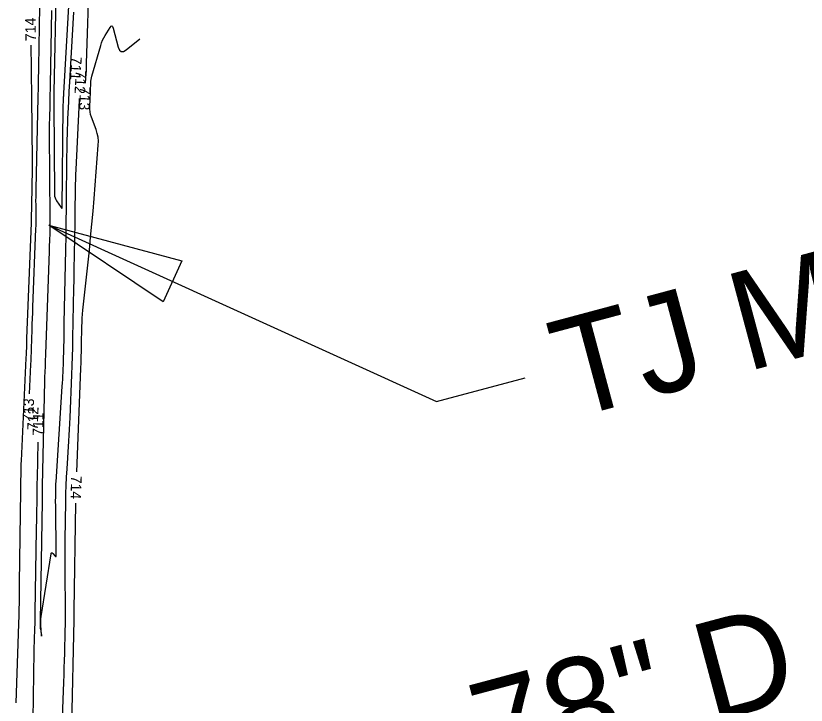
# Model space of a CAD drawing. Extents: x -361782338 to 28259792, y -263199453 to 8342113.
# Drawn here: x 1403883.2 to 1404183.4, y 578042.3 to 578304.2 of the extents above; entities that cross this region are included whole.
import ezdxf

# ---------------------------------------------------------------- set-up
doc = ezdxf.new("R2010")
doc.units = 0
for name, color, linetype in [('DT_X_Contour_Minor', 7, 'Continuous'), ('Level 19', 7, 'Continuous'), ('Level 40', 7, 'Continuous')]:
    doc.layers.add(name, color=color, linetype=linetype)

msp = doc.modelspace()

# ---------------------------------------------------------------- linework, layer by layer
at = {"layer": 'DT_X_Contour_Minor'}
for points in [[(1403900.29, 578367.2), (1403898.68, 578324.89), (1403898.65, 578324.11), (1403898.63, 578323.33), (1403898.61, 578322.55), (1403898.59, 578321.77), (1403898.55, 578319.22), (1403898.54, 578318.67), (1403898.53, 578318.13), (1403898.51, 578317.58), (1403898.5, 578317.03), (1403897.68, 578275.22), (1403897.67, 578274.75), (1403897.66, 578274.28), (1403897.65, 578273.81), (1403897.64, 578273.35), (1403897.6, 578271.81), (1403897.6, 578271.49), (1403897.59, 578271.16), (1403897.59, 578270.83), (1403897.59, 578270.5)], [(1403892.48, 578323.08), (1403891.81, 578284.88), (1403891.79, 578283.71), (1403891.77, 578282.55), (1403891.74, 578281.38), (1403891.72, 578280.21), (1403891.65, 578276.4), (1403891.63, 578275.58), (1403891.61, 578274.77), (1403891.6, 578273.95), (1403891.58, 578273.13), (1403890.78, 578238.34), (1403890.75, 578236.86), (1403890.74, 578235.37), (1403890.73, 578233.89), (1403890.74, 578232.4), (1403890.78, 578227.55), (1403890.78, 578226.51), (1403890.78, 578225.47), (1403890.75, 578224.43), (1403890.72, 578223.39), (1403889.57, 578193.43), (1403889.49, 578191.27), (1403889.41, 578189.12), (1403889.34, 578186.96), (1403889.26, 578184.81), (1403889.02, 578177.76), (1403888.97, 578176.25), (1403888.91, 578174.74), (1403888.84, 578173.24), (1403888.77, 578171.73), (1403888.25, 578160.57)], [(1403909.71, 578278.52), (1403909.93, 578282.21), (1403909.98, 578283.17), (1403910.03, 578284.13), (1403910.07, 578285.08), (1403910.1, 578286.04), (1403911.22, 578320.68)], [(1403897.59, 578270.5), (1403897.89, 578236.36), (1403897.94, 578235.68), (1403898.09, 578235.04), (1403898.34, 578234.43), (1403898.67, 578233.85), (1403900.43, 578231.28), (1403900.46, 578231.24), (1403900.49, 578231.22), (1403900.52, 578231.19), (1403900.56, 578231.17), (1403900.69, 578231.11), (1403900.72, 578231.1), (1403900.74, 578231.11), (1403900.75, 578231.12), (1403900.75, 578231.15), (1403901.22, 578269.6), (1403901.23, 578270.11), (1403901.24, 578270.63), (1403901.26, 578271.15), (1403901.28, 578271.66), (1403901.36, 578273.35), (1403901.38, 578273.71), (1403901.4, 578274.07), (1403901.42, 578274.43), (1403901.44, 578274.79), (1403903.86, 578316.79)], [(1403892.45, 578074.21), (1403892.42, 578072.56), (1403892.42, 578072.21), (1403892.44, 578071.85), (1403892.47, 578071.5), (1403892.52, 578071.14), (1403892.9, 578068.91), (1403892.97, 578068.55), (1403893, 578068.44), (1403893.01, 578068.56), (1403892.99, 578068.92), (1403892.72, 578072.7), (1403892.69, 578073.51), (1403892.7, 578074.31), (1403892.75, 578075.12), (1403892.85, 578075.92), (1403896.56, 578099.73), (1403896.65, 578100.05), (1403896.79, 578100.19), (1403896.99, 578100.15), (1403897.23, 578099.92), (1403898.13, 578098.89), (1403898.3, 578098.73), (1403898.41, 578098.7), (1403898.48, 578098.8), (1403898.51, 578099.03), (1403898.33, 578118.4), (1403898.32, 578119.26), (1403898.32, 578120.13), (1403898.33, 578120.99), (1403898.34, 578121.85), (1403898.38, 578124.67), (1403898.4, 578125.27), (1403898.42, 578125.87), (1403898.44, 578126.48), (1403898.48, 578127.08), (1403900.85, 578163.37), (1403900.93, 578164.7), (1403901, 578166.02), (1403901.07, 578167.35), (1403901.12, 578168.68), (1403901.29, 578173.01), (1403901.33, 578173.94), (1403901.36, 578174.87), (1403901.38, 578175.8), (1403901.4, 578176.73), (1403901.52, 578182.51), (1403901.54, 578183.75), (1403901.57, 578184.99), (1403901.59, 578186.23), (1403901.62, 578187.47), (1403902.16, 578215.27), (1403902.26, 578220.56), (1403902.35, 578225.84), (1403902.43, 578231.13), (1403902.5, 578236.42), (1403902.75, 578257.12), (1403902.79, 578259.1), (1403902.84, 578261.09), (1403902.9, 578263.07), (1403902.99, 578265.05), (1403903.29, 578271.53), (1403903.36, 578272.91), (1403903.43, 578274.3), (1403903.51, 578275.69), (1403903.58, 578277.08), (1403905.23, 578305.54)], [(1403896.78, 578306.21), (1403896.22, 578278.06), (1403896.18, 578276.23), (1403896.15, 578274.4), (1403896.11, 578272.57), (1403896.06, 578270.75), (1403895.93, 578264.77), (1403895.9, 578263.49), (1403895.89, 578262.21), (1403895.89, 578260.93), (1403895.89, 578259.65), (1403896.17, 578227.35), (1403896.17, 578226.08), (1403896.16, 578224.81), (1403896.14, 578223.54), (1403896.1, 578222.28), (1403895.94, 578218.13), (1403895.9, 578217.25), (1403895.87, 578216.36), (1403895.84, 578215.47), (1403895.81, 578214.58), (1403894.48, 578175.72), (1403894.44, 578174.7), (1403894.4, 578173.68), (1403894.36, 578172.65), (1403894.31, 578171.63), (1403894.16, 578168.29), (1403894.13, 578167.57), (1403894.1, 578166.85), (1403894.08, 578166.14), (1403894.06, 578165.42), (1403893.26, 578125.55), (1403893.25, 578124.96), (1403893.24, 578124.38), (1403893.23, 578123.8), (1403893.22, 578123.22), (1403893.2, 578121.31), (1403893.19, 578120.91), (1403893.19, 578120.5), (1403893.18, 578120.09), (1403893.18, 578119.68), (1403892.45, 578074.35), (1403892.45, 578074.34), (1403892.45, 578074.33), (1403892.45, 578074.31), (1403892.45, 578074.3), (1403892.45, 578074.25), (1403892.45, 578074.24), (1403892.45, 578074.23), (1403892.45, 578074.22), (1403892.45, 578074.21)], [(1403906.37, 578130.97), (1403907.91, 578170.21), (1403907.99, 578172.4), (1403908.06, 578174.6), (1403908.12, 578176.8), (1403908.17, 578179), (1403908.31, 578186.18), (1403908.36, 578187.72), (1403908.44, 578189.25), (1403908.55, 578190.79), (1403908.7, 578192.32), (1403911.12, 578215.18), (1403911.62, 578220.08), (1403912.09, 578224.98), (1403912.52, 578229.89), (1403912.92, 578234.8), (1403914.5, 578255.06), (1403914.54, 578256.57), (1403914.41, 578258.05), (1403914.12, 578259.51), (1403913.67, 578260.95), (1403911.93, 578265.61), (1403911.61, 578266.61), (1403911.39, 578267.63), (1403911.28, 578268.67), (1403911.28, 578269.73), (1403911.53, 578275.12), (1403911.54, 578275.18), (1403911.54, 578275.24), (1403911.54, 578275.29), (1403911.55, 578275.35), (1403911.56, 578275.54), (1403911.56, 578275.58), (1403911.56, 578275.62), (1403911.56, 578275.66), (1403911.56, 578275.7), (1403911.66, 578278.69), (1403911.7, 578279.33), (1403911.78, 578279.96), (1403911.9, 578280.59), (1403912.06, 578281.21), (1403915.45, 578292.86), (1403915.78, 578293.87), (1403916.18, 578294.86), (1403916.64, 578295.81), (1403917.18, 578296.74), (1403919.03, 578299.71), (1403919.4, 578300.18), (1403919.72, 578300.3), (1403919.98, 578300.09), (1403920.2, 578299.53), (1403922.13, 578292.21), (1403922.59, 578291.12), (1403923.23, 578290.59), (1403924.06, 578290.64), (1403925.07, 578291.24), (1403930.24, 578295.4)], [(1403888.88, 578293.01), (1403889.02, 578284.14), (1403889.03, 578283.06), (1403889.05, 578281.98), (1403889.07, 578280.9), (1403889.08, 578279.82), (1403889.14, 578276.3), (1403889.15, 578275.54), (1403889.16, 578274.79), (1403889.17, 578274.03), (1403889.17, 578273.28), (1403889.35, 578249.11), (1403889.36, 578246.49), (1403889.35, 578243.87), (1403889.32, 578241.26), (1403889.27, 578238.64), (1403889, 578226.65), (1403889, 578226.54), (1403889, 578226.43), (1403889, 578226.32), (1403889, 578226.2), (1403889, 578225.84), (1403889, 578225.77), (1403889, 578225.69), (1403889, 578225.61), (1403889, 578225.54), (1403887.31, 578181.52), (1403887.28, 578180.78), (1403887.26, 578180.04), (1403887.23, 578179.3), (1403887.2, 578178.56), (1403887.12, 578176.14), (1403887.1, 578175.62), (1403887.08, 578175.1), (1403887.06, 578174.58), (1403887.04, 578174.06), (1403885.21, 578135.1), (1403885.16, 578133.97), (1403885.12, 578132.83), (1403885.09, 578131.7), (1403885.06, 578130.56), (1403884.98, 578126.86), (1403884.97, 578126.06), (1403884.96, 578125.27), (1403884.94, 578124.48), (1403884.93, 578123.68), (1403884.49, 578088.59), (1403884.47, 578087.05), (1403884.45, 578085.52), (1403884.43, 578083.98), (1403884.41, 578082.45), (1403884.33, 578077.43), (1403884.31, 578076.36), (1403884.28, 578075.28), (1403884.25, 578074.21), (1403884.22, 578073.14), (1403883.19, 578043.13)], [(1403900.67, 578030.84), (1403901.43, 578051.04), (1403901.52, 578053.76), (1403901.61, 578056.48), (1403901.69, 578059.2), (1403901.76, 578061.92), (1403901.97, 578070.81), (1403902.01, 578072.71), (1403902.03, 578074.62), (1403902.03, 578076.52), (1403902.02, 578078.42), (1403901.89, 578092.78), (1403901.88, 578095.86), (1403901.88, 578098.93), (1403901.89, 578102.01), (1403901.93, 578105.08), (1403902.15, 578119.58), (1403902.22, 578122.69), (1403902.33, 578125.79), (1403902.47, 578128.9), (1403902.65, 578132), (1403903.34, 578142.54), (1403903.48, 578144.8), (1403903.61, 578147.06), (1403903.72, 578149.32), (1403903.81, 578151.59), (1403904.45, 578167.79), (1403904.58, 578171.26), (1403904.69, 578174.74), (1403904.79, 578178.21), (1403904.86, 578181.68), (1403905.25, 578200.68), (1403905.3, 578203.55), (1403905.36, 578206.41), (1403905.42, 578209.28), (1403905.47, 578212.15), (1403905.66, 578221.51), (1403905.69, 578223.51), (1403905.73, 578225.52), (1403905.76, 578227.53), (1403905.78, 578229.53), (1403905.89, 578238.26), (1403905.92, 578240.13), (1403905.97, 578242), (1403906.03, 578243.87), (1403906.11, 578245.74), (1403907.23, 578269.41), (1403907.36, 578272.09), (1403907.4, 578272.79)], [(1403891.52, 578142.23), (1403891.24, 578128.46), (1403891.21, 578126.53), (1403891.17, 578124.6), (1403891.14, 578122.68), (1403891.12, 578120.75), (1403891.04, 578114.45), (1403891.02, 578113.1), (1403891, 578111.75), (1403890.98, 578110.4), (1403890.96, 578109.05), (1403890.46, 578077.51), (1403890.43, 578076.04), (1403890.4, 578074.57), (1403890.36, 578073.09), (1403890.31, 578071.62), (1403890.14, 578066.82), (1403890.11, 578065.79), (1403890.08, 578064.76), (1403890.06, 578063.73), (1403890.04, 578062.7), (1403889.61, 578036.78)], [(1403904.42, 578034.73), (1403905.37, 578074.7), (1403905.37, 578075.05), (1403905.38, 578075.4), (1403905.38, 578075.75), (1403905.38, 578076.1), (1403905.37, 578077.25), (1403905.36, 578077.49), (1403905.36, 578077.74), (1403905.37, 578077.99), (1403905.37, 578078.23), (1403905.99, 578118.98)]]:
    msp.add_lwpolyline(points, dxfattribs=at)
at = {"layer": 'Level 40'}
for p, q in [((1403895.77, 578224.64), (1404043.03, 578157.66)), ((1403939.16, 578195.46), (1403895.77, 578224.64)), ((1403895.77, 578224.64), (1403946.27, 578211.09)), ((1403946.27, 578211.09), (1403939.16, 578195.46)), ((1404043.03, 578157.66), (1404076.65, 578166.67))]:
    msp.add_line(p, q, dxfattribs=at)

# ---------------------------------------------------------------- texts
at = {"layer": 'Level 19'}
for s, rotation, p in [('714', 90.9057, (1403890.85, 578294.57)), ('711', 266.7034, (1403904.27, 578288.75)), ('712', 266.8276, (1403905.98, 578283.53)), ('713', 267.1225, (1403907.63, 578277.3)), ('713', 87.3165, (1403889.75, 578149.81)), ('712', 87.9088, (1403891.52, 578146.67)), ('711', 88.8513, (1403893.57, 578144.53)), ('714', 268.2264, (1403904.23, 578129.51))]:
    msp.add_text(s, height=4, rotation=rotation, dxfattribs=at).set_placement(p)
at = {"layer": 'Level 40'}
for s, p in [('TJ McCARTHY DT.', (1404093.28, 578150.83)), ('78" D', (1404062.6, 578012.9))]:
    msp.add_text(s, height=37.5, rotation=15, dxfattribs=at).set_placement(p)

doc.saveas('drawing.dxf')
